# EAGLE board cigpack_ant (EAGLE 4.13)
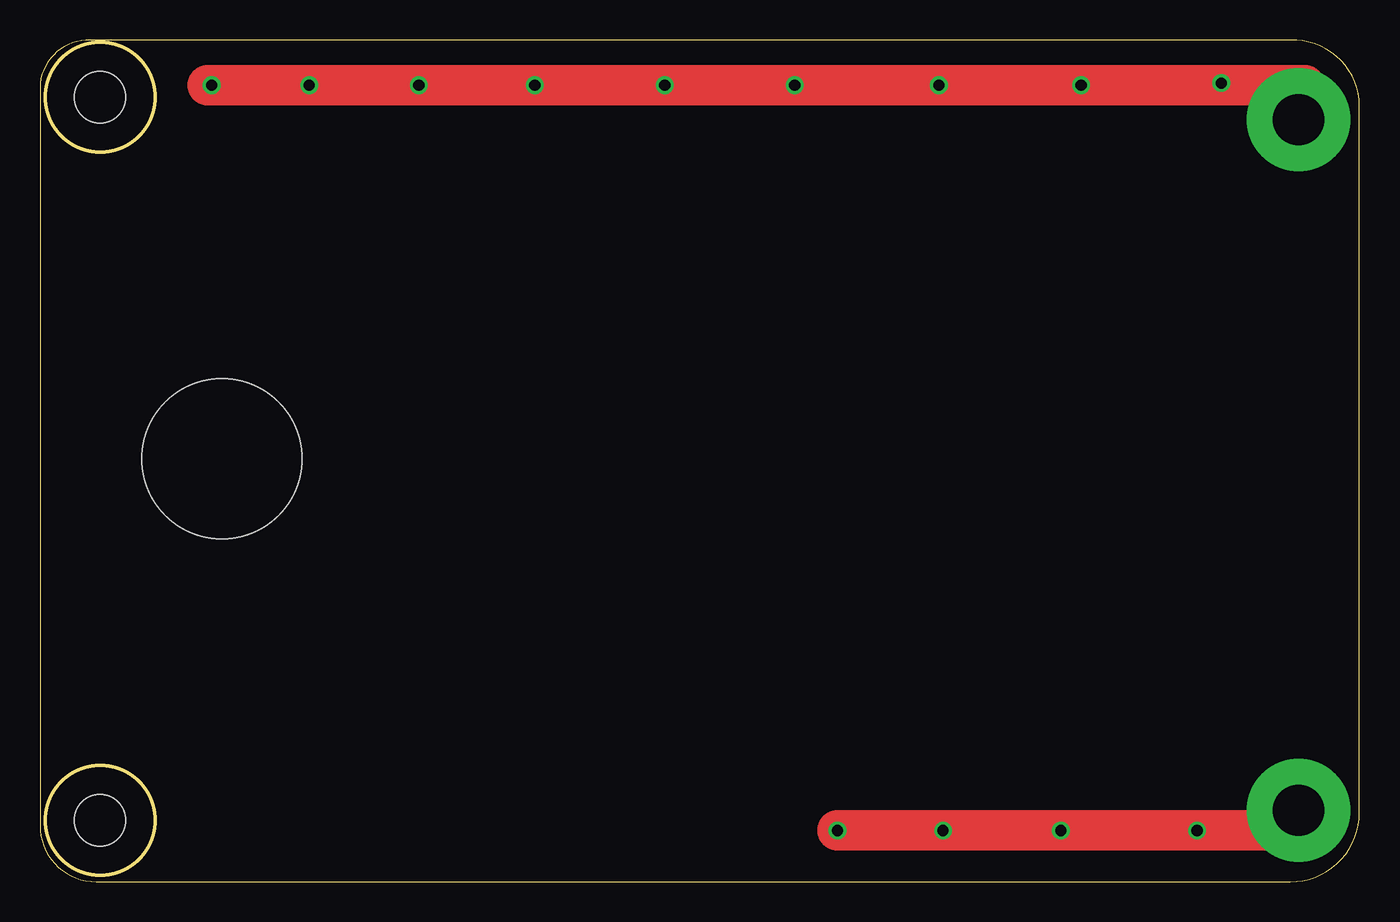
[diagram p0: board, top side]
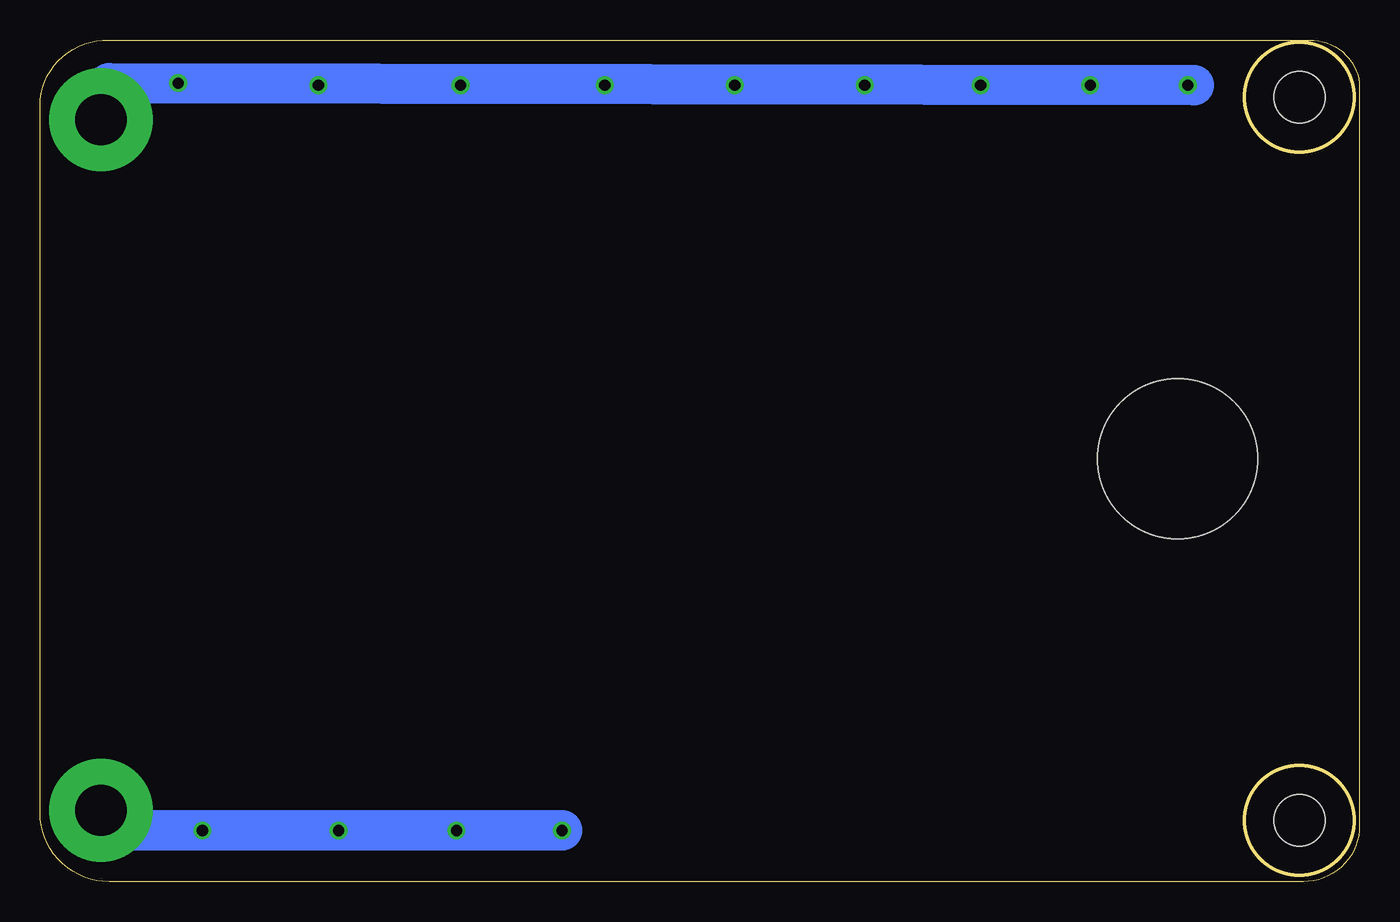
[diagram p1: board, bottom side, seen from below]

Size 82.49 x 52.63 mm. Coordinates in mm from the lower left corner, seen from the top.
Outline: 3.43,52.6 arc90 0,49.93 0,3.52 arc90 3.52,0 78.16,0 arc90 82.49,4.33 82.49,48.9 arc90 77.78,52.6 3.43,52.6
Outline: circle at 3.75,3.83 radius 3.43
Outline: circle at 3.75,49.05 radius 3.43
Copper layers (1*16): Top 0.035mm / dielectric 1.5mm / Bottom 0.035mm
Design rules "default": minimum track width 10mil, minimum drill 24mil, track to track 8mil, track to pad 8mil, pad to pad 8mil, via to via 8mil, smd to smd 8mil, copper to edge 40mil, drill to drill 8mil, minimum pad ring 10mil, minimum via ring 8mil, stop-mask expansion 4mil, vias tented up to drill 0mil, thermal gap 10mil
Holes 3.2 mm at 3.75,3.83 3.75,49.05
Holes 10 mm at 11.37,26.44

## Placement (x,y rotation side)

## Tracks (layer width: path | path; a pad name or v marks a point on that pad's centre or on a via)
19GHZANT  (via drill 0.7, 3.2 pad 6.45)
  Top 0.305: 78.94,4.34 79.06,4.47 | 78.94,4.34 78.81,4.34 78.81,3.2 | 78.94,4.34 v78.68,4.47
  Top 2.54: v49.85,3.2 v56.46,3.2 v63.82,3.2 v72.33,3.2 78.81,3.2
  Bottom 2.54: v49.85,3.2 v56.46,3.2 v63.82,3.2 v72.33,3.2 78.17,3.2 78.94,3.45 v78.68,4.47
800MHZANT  (via drill 0.7, 3.2 pad 6.45)
  Top 0.305: 79.06,49.81 79.7,49.17 v78.68,47.65
  Top 0.406: v73.86,49.94 73.6,50.19 73.22,49.81 69.79,49.81
  Top 2.54: 10.48,49.81 v10.74,49.81 v16.83,49.81 v23.69,49.81 v30.93,49.81 v39.06,49.81 v47.19,49.81 v56.2,49.81 v65.09,49.81 69.79,49.81 79.06,49.81
  Bottom 2.54: v78.68,47.65 78.94,49.55 78.17,49.94 10.36,49.81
